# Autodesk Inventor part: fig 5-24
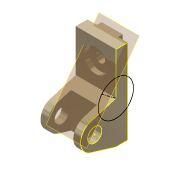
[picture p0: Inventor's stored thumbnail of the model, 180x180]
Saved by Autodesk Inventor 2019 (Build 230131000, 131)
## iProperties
Shininess: 65.0
Angle Display Precision: 2
Document Length Units: 11269
Document Angle Units: 11279
Document Time Units: 11290
Document Mass Units: 11283
Document Length Units Precision: 3
Document Angle Units Precision: 2
Compacted: False
Created: 2001-11
Part Number: fig 5-24
Document SubType Name: Modeling
Designer: Renu Muthoo
Density: 1 g/cm^3
Material: Generic
Appearance: Metal-Titanium (Polished)
Density: 0.0
Volumn: 0.0
Area: 0.0
PropertySet Name: Model Information
Control State: 0
Master: False
Checked Out: False
Author: Renu Muthoo
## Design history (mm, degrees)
node "Sketch1"
sketch "Sketch2"
  geometry: L1 (33.257, 104.664)-(33.257, -75.336); L2 (33.257, -75.336)-(8.257, -75.336); L3 (8.257, -75.336)-(-45.451, -59.045); L4 (-45.451, -1.628)-(8.257, 14.664); L5 (8.257, 14.664)-(8.257, 104.664); L6 (8.257, 104.664)-(33.257, 104.664); C1 r 15 at (-36.743, -30.336); A1 r 30 centre (-36.743, -30.336) between (-45.451, -1.628) and (-45.451, -59.045)
  constraints: 12 end point, 2 centre point, 2 equal length, 2 parallel, 2 point on circle, 2 tangent, 1 coincident, 1 perpendicular, 1 vertical
  dimensions: "d0" = 180 distance of L1.start L1.end; "d1" = 30 radius of A1; "d2" = 25 distance of L5.end L1.start; "d3" = 45 distance from line of L2 A1.centre; "d4" = 70 distance from line of L1 A1.centre; "d5" = 30 diameter of C1
extrude "Extrusion1" new body sketch "Sketch2" distance "d6" = 85; taper "d7" = 0 deg
workplane "Work Plane1"
sketch "Sketch3"
  geometry: L1 (15, 62.364)-(70, 62.364); L2 (70, 62.364)-(70, -52.386); L3 (70, -52.386)-(15, -52.386); L4 (15, -52.386)-(15, 62.364); L5 (0, -45)-(0, -28.708) reference
  constraints: 8 end point, 2 parallel, 1 horizontal, 1 perpendicular
  dimensions: "d8" = 55 distance of L1.start L1.end; "d9" = 15 distance between parallel lines of L5 L4
extrude "Extrusion2" cut sketch "Sketch3" distance "d10" = 50; taper "d11" = 0 deg
sketch "Sketch4"
  geometry: L1 (0, 25)-(85, 25) reference; L2 (0, 0)-(0, 25) reference; L3 (20, 25)-(65, 25); L4 (65, 25)-(65, 35); L5 (65, 35)-(20, 35); L6 (20, 35)-(20, 25)
  constraints: 8 end point, 2 parallel, 1 horizontal, 1 perpendicular, 1 point on line
  dimensions: "d12" = 45 distance of L4.end L5.end; "d13" = 10 distance of L3.end L4.end; "d14" = 20 distance between parallel lines of L2 L6
extrude "Extrusion3" join sketch "Sketch4" stored distance "d15" = 50; taper "d16" = 0 deg
sketch "Sketch5"
  geometry: L1 (85, 0)-(85, 90) reference; L2 (0, 90)-(85, 90) reference; 1 further point
  dimensions: "d17" = 42 distance from line of L2 point (42.5, 48); "d18" = 42.5 distance from line of L1 point (42.5, 48)
hole "Hole1" sketch "Sketch5" at (42.5, 48) diameter "d19" = 20; stored, may be unused: countersink angle "d23" = 82 deg, drill point angle "d25" = 118 deg; dims "d20" = 6, "d21" = 50, "d22" = 10, "d24" = 8
sketch "Sketch8"
  geometry: L1 (75.336, 33.257)-(75.336, 8.257) reference; L2 (-104.664, 33.257)-(75.336, 33.257) reference; L3 (-104.664, 8.257)-(-104.664, 33.257) reference; L4 (-14.664, 8.257)-(-104.664, 8.257) reference; L5 (1.628, -45.451)-(-14.664, 8.257) reference; L6 (75.336, 8.257)-(59.045, -45.451) reference; C1 r 15 at (30.336, -36.743) reference; C2 r 37.437 at (-14.664, 8.257); A1 r 30 centre (30.336, -36.743) between (1.628, -45.451) and (59.045, -45.451) reference
  constraints: 1 centre point, 1 coincident
sketch "Sketch9"
  geometry: L1 (75.336, 33.257)-(75.336, 8.257) reference; L2 (-14.664, 8.257)-(-104.664, 8.257) reference; L3 (1.628, -45.451)-(-14.664, 8.257) reference; L4 (75.336, 8.257)-(59.045, -45.451) reference; L5 (-14.664, 8.257)-(-37, -21.743); C1 r 15 at (30.336, -36.743) reference; A1 r 30 centre (30.336, -36.743) between (1.628, -45.451) and (59.045, -45.451) reference
  constraints: 2 end point
workplane "Work Plane11"
body "Solid1"
